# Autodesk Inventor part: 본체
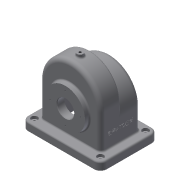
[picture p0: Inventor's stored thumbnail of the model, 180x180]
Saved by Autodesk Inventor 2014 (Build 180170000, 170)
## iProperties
Created: 2017-11
Part Number: 본체
Material: Generic
Document SubType Name: Modeling
Designer: user
Density: 1 g/cm^3
Appearance: Default
Mass: 398.334 g
Surface Area: 1182.07 cm^2
Volume: 398.334 cm^3
Author: user
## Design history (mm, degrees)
sketch "스케치1"
  geometry: L1 (-75, 55)-(75, 55); L2 (75, 55)-(75, -55); L3 (75, -55)-(-75, -55); L4 (-75, -55)-(-75, 55); L5 (-75, 55)-(75, -55); L6 (75, 55)-(-75, -55); 1 further point
  constraints: 12 end point, 2 midpoint, 2 parallel, 1 horizontal, 1 perpendicular
  dimensions: "d0" = 150 distance of L2.end L3.end; "d1" = 110 distance of L1.end L2.end
extrude "돌출1" new body sketch "스케치1" distance "d2" = 15; taper "d3" = 0 deg
sketch "스케치2"
  geometry: L1 (58, 0)-(-58, 0); L2 (-58, 0)-(-58, 80); L3 (-58, 80)-(58, 80); L4 (58, 80)-(58, 0); L5 (58, 0)-(-58, 80); L6 (-58, 0)-(58, 80); L7 (0, 0)-(0, 40); 1 further point
  constraints: 14 end point, 3 midpoint, 3 parallel, 1 horizontal, 1 perpendicular
  dimensions: "d5" = 116 distance of L2.end L3.end; "d6" = 80 distance of L1.end L2.end; "d7" = 40 distance of L7.end L7.start
extrude "돌출2" join sketch "스케치2" distance "d8" = 38; taper "d9" = 0 deg
sketch "스케치3"
  geometry: L1 (-58, 80)-(-58, 15) reference; L2 (0, 0)-(0, 28.5); L3 (58, 0)-(-58, 0); L4 (-58, 0)-(-58, 57); L5 (-58, 57)-(58, 57); L6 (58, 57)-(58, 0); L7 (58, 0)-(-58, 57); L8 (-58, 0)-(58, 57)
  constraints: 14 end point, 3 parallel, 2 midpoint, 1 horizontal, 1 perpendicular
  dimensions: "d10" = 28.5 distance of L2.start L2.end; "d11" = 116 distance of L4.end L5.end; "d12" = 57 distance of L3.end L4.end
extrude "돌출3" join sketch "스케치3" distance "d13" = 38; taper "d14" = 0 deg
sketch "스케치4"
  geometry: L1 (58, 80)-(-58, 80) reference; 2 further points
  constraints: 1 horizontal alignment, 1 midpoint, 2 other
extrude "돌출4" join sketch "스케치4" distance "d15" = 38; taper "d16" = 0 deg
sketch "스케치5"
  geometry: L1 (-58, 57)-(58, 57) reference; L2 (-75, 0)-(75, 0) reference; L3 (-10.724, 0)-(10.724, 0); A1 r 58 centre (0, 57) between (10.724, 0) and (-10.724, 0); 1 further point
  constraints: 3 point on circle, 2 end point, 2 point on line, 1 centre point, 1 collinear, 1 midpoint
extrude "돌출5" join sketch "스케치5" distance "d17" = 38; taper "d18" = 0 deg
sketch "스케치6"
  geometry: L1 (58, 15)-(58, 80) reference; L2 (0, 0)-(0, 65); C1 r 37.5 at (0, 65)
  constraints: 2 end point, 1 centre point, 1 coincident, 1 parallel
  dimensions: "d19" = 65 distance of L2.start L2.end; "d20" = 75 diameter of C1
extrude "돌출6" join sketch "스케치6" distance "d21" = 9; taper "d22" = 0 deg
sketch "스케치7"
  geometry: L1 (-58, 57)-(-58, 15) reference; L2 (0, 0)-(0, 65); C1 r 31 at (0, 65)
  constraints: 2 end point, 1 centre point, 1 coincident, 1 parallel
  dimensions: "d23" = 65 distance of L2.start L2.end; "d24" = 62 diameter of C1
extrude "돌출7" join sketch "스케치7" distance "d25" = 10; taper "d26" = 0 deg
sketch "스케치8"
  geometry: C1 r 37.5 at (0, 0) reference; C2 r 16 at (0, 0); 1 further point
  constraints: 1 centre point, 1 coincident
  dimensions: "d27" = 32 diameter of C2
extrude "돌출8" cut sketch "스케치8" distance "d28" = 95; taper "d29" = 0 deg
sketch "스케치9"
  geometry: L1 (53, -33)-(-53, -33); L2 (-53, -33)-(-53, 33); L3 (-53, 33)-(53, 33); L4 (53, 33)-(53, -33); L5 (53, -33)-(-53, 33); L6 (-53, -33)-(53, 33); 1 further point
  constraints: 12 end point, 2 midpoint, 2 parallel, 1 horizontal, 1 perpendicular
  dimensions: "d30" = 106 distance of L2.end L3.end; "d31" = 66 distance of L1.end L2.end
extrude "돌출9" cut sketch "스케치9" distance "d32" = 57; taper "d33" = 0 deg
sketch "스케치10"
  geometry: L1 (102.5, 47)-(27.5, 47) reference; L2 (57, 33)-(57, -33) reference; L3 (57, -33)-(57, 11.323); L4 (57, -33)-(110, -33); L5 (110, -33)-(110, 5); L6 (110, 5)-(57, 5); 1 further point
  constraints: 8 end point, 2 perpendicular, 2 point on line
  dimensions: "d34" = 53 distance of L2.end L4.end; "d35" = 38 distance of L4.end L5.end; "d36" = 53 distance of L5.end L6.end
revolve "회전1" sketch "스케치10" stored, may be unused: angle "d37" = 90 deg
sketch "스케치11"
  geometry: L1 (80, 38)-(138, 38) reference; L2 (138, 38)-(138, 0) reference; L3 (80, 38)-(85, 38); L4 (80, 33)-(133, 33); L5 (133, 33)-(133, 5); L6 (133, 5)-(80, 5); L7 (80, 33)-(80, 5); 1 further point
  constraints: 10 end point, 2 perpendicular, 1 horizontal, 1 parallel
  dimensions: "d39" = 5 distance of L1.start L4.start; "d41" = 53 distance of L4.start L4.end; "d42" = 28 distance of L4.end L5.end
revolve "회전2" sketch "스케치11" stored, may be unused: angle "d43" = 90 deg
sketch "스케치12"
  geometry: L1 (-53, -33)-(-53, 33) reference; L2 (-53, 33)-(53, 33) reference; L3 (-53, 5)-(-47.749, 5) reference; L4 (47.749, 33)-(47.749, 5) reference; L5 (47.749, 5)-(53, 5) reference; L6 (53, 33)-(53, 5) reference; L7 (47.749, 33)-(53, 33) reference; L8 (-47.749, 5)-(-47.749, 33) reference; L9 (-47.749, 5)-(-47.749, 33) reference; L10 (-53, 33)-(-47.749, 33) reference; L11 (-53, 5)-(-53, 33) reference; L12 (-53, 5)-(-47.749, 5) reference; 1 further point
extrude "돌출10" cut sketch "스케치12" distance "d44" = 80; taper "d45" = 0 deg
sketch "스케치13" dims "d46" = 58
  geometry: C1 r 37.5 at (0, 0) reference; C2 r 1.5 at (0, 29); C3 r 1.5 at (-29, 0); C4 r 1.5 at (0, -29); C5 r 1.5 at (29, 0); 5 further points
  constraints: 4 centre point, 4 coincident, 1 vertical alignment, 11 other
  dimensions: "d47" = 3 diameter of C2; "d50" = 360 deg dimension on point (0, 0) C2.centre (derived)
hole "구멍1" sketch "스케치13" at (0, 29), (-29, 0), (0, -29), (29, 0) diameter "d52" = 2.459; stored, may be unused: countersink angle "d56" = 90 deg, drill point angle "d58" = 118 deg; dims "d53" = 6, "d54" = 4, "d55" = 2, "d57" = 8
sketch "스케치14" dims "d59" = 52
  geometry: C1 r 31 at (0, 0) reference; C2 r 1.5 at (-26, 0); C3 r 1.5 at (0, -26); C4 r 1.5 at (26, 0); C5 r 1.5 at (0, 26); 2 further points
  constraints: 4 centre point, 1 coincident, 1 horizontal alignment, 11 other
  dimensions: "d60" = 3 diameter of C2; "d63" = 360 deg dimension on point (0, 0) C2.centre (derived)
hole "구멍2" sketch "스케치14" at (0, 26), (26, 0), (0, -26), (-26, 0) diameter "d65" = 2.459; stored, may be unused: countersink angle "d69" = 90 deg, drill point angle "d71" = 118 deg; dims "d66" = 6, "d67" = 4, "d68" = 2, "d70" = 8
fillet "모깎기1" dims "d72" = 12
sketch "스케치15"
  geometry: A1 r 12 centre (-63, 43) between (-63, 55) and (-75, 43) reference; A2 r 12 centre (-63, -43) between (-75, -43) and (-63, -55) reference; A3 r 12 centre (63, -43) between (63, -55) and (75, -43) reference; A4 r 12 centre (63, 43) between (75, 43) and (63, 55) reference; 1 further point
hole "구멍3" sketch "스케치15" at (-63, -43), (63, -43), (63, 43), (-63, 43) diameter "d73" = 5; stored, may be unused: countersink angle "d77" = 90 deg, drill point angle "d79" = 118 deg; dims "d74" = 6, "d75" = 12, "d76" = 5, "d78" = 8
node "작업 평면2"
sketch "스케치17"
  geometry: L1 (-58, 38)-(58, 38) reference; L2 (0, 38)-(0, 19); C1 r 6 at (0, 19); 1 further point
  constraints: 2 end point, 1 centre point, 1 coincident, 1 midpoint, 1 perpendicular
  dimensions: "d82" = 19 distance of L2.start L2.end; "d83" = 12 diameter of C1
extrude "돌출11" join sketch "스케치17" stored distance "d84" = 80; taper "d85" = 0 deg
sketch "스케치18"
  geometry: C1 r 6 at (0, 0) reference; 1 further point
hole "구멍4" sketch "스케치18" at (0, 0) diameter "d86" = 4.459; stored, may be unused: countersink angle "d90" = 90 deg, drill point angle "d92" = 118 deg; dims "d87" = 25, "d88" = 12, "d89" = 5, "d91" = 8
fillet "모깎기2" dims "d93" = 3
chamfer "모따기1" distance "d94" = 1; stored, may be unused: second distance "d95" = 2, angle "d96" = 45 deg
fillet "모깎기3" dims "d101" = 8
fillet "모깎기4" dims "d102" = 3
sketch "스케치20"
  geometry: L1 (-35, 23)-(-35, -39) reference; L2 (-40, -57)-(-52, -57) reference; 2 further points
  constraints: 1 other
  dimensions: "d103" = 38 distance from line of point (3, -17) L1; "d104" = 40 distance from line of L2 point (3, -17)
feature "엠보싱2" sketch "스케치20" dims "d0" = 150, "d1" = 110, "d10" = 28.5, "d11" = 116, "d12" = 57, "d105" = 0.5, "d106" = 0
node "솔리드1"
node "투영된 루프1"
node "투영된 루프2"
other parameters: "d81" = -144
